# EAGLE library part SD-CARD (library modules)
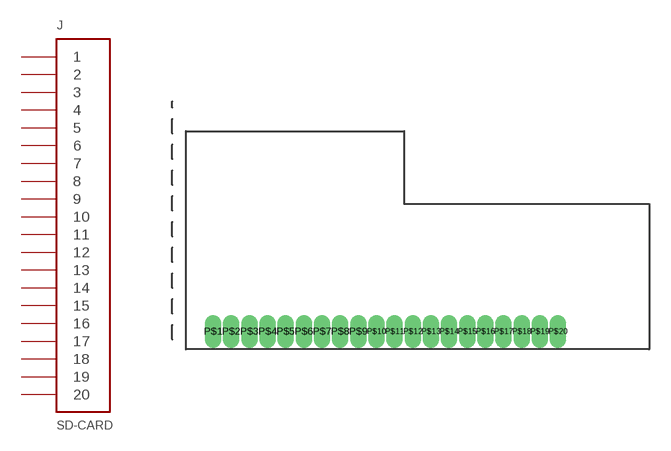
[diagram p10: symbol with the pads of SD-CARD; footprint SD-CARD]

Designator prefix J

## SD-CARD  [SD-CARD]
P$1  1
P$2  2
P$3  3
P$4  4
P$5  5
P$6  6
P$7  7
P$8  8
P$9  9
P$10  10
P$11  11
P$12  12
P$13  13
P$14  14
P$15  15
P$16  16
P$17  17
P$18  18
P$19  19
P$20  20

## Footprint SD-CARD (pad centres in mm)
drill 0.66 pad 1.016 long: P$1 -10.175,-0.02; P$2 -8.905,-0.02; P$3 -7.635,-0.02; P$4 -6.365,-0.02; P$5 -5.095,-0.02; P$6 -3.825,-0.02; P$7 -2.555,-0.02; P$8 -1.285,-0.02; P$9 -0.015,-0.02; P$10 1.255,-0.02; P$11 2.525,-0.02; P$12 3.795,-0.02; P$13 5.065,-0.02; P$14 6.335,-0.02; P$15 7.605,-0.02; P$16 8.875,-0.02; P$17 10.145,-0.02; P$18 11.415,-0.02; P$19 12.685,-0.02; P$20 13.955,-0.02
